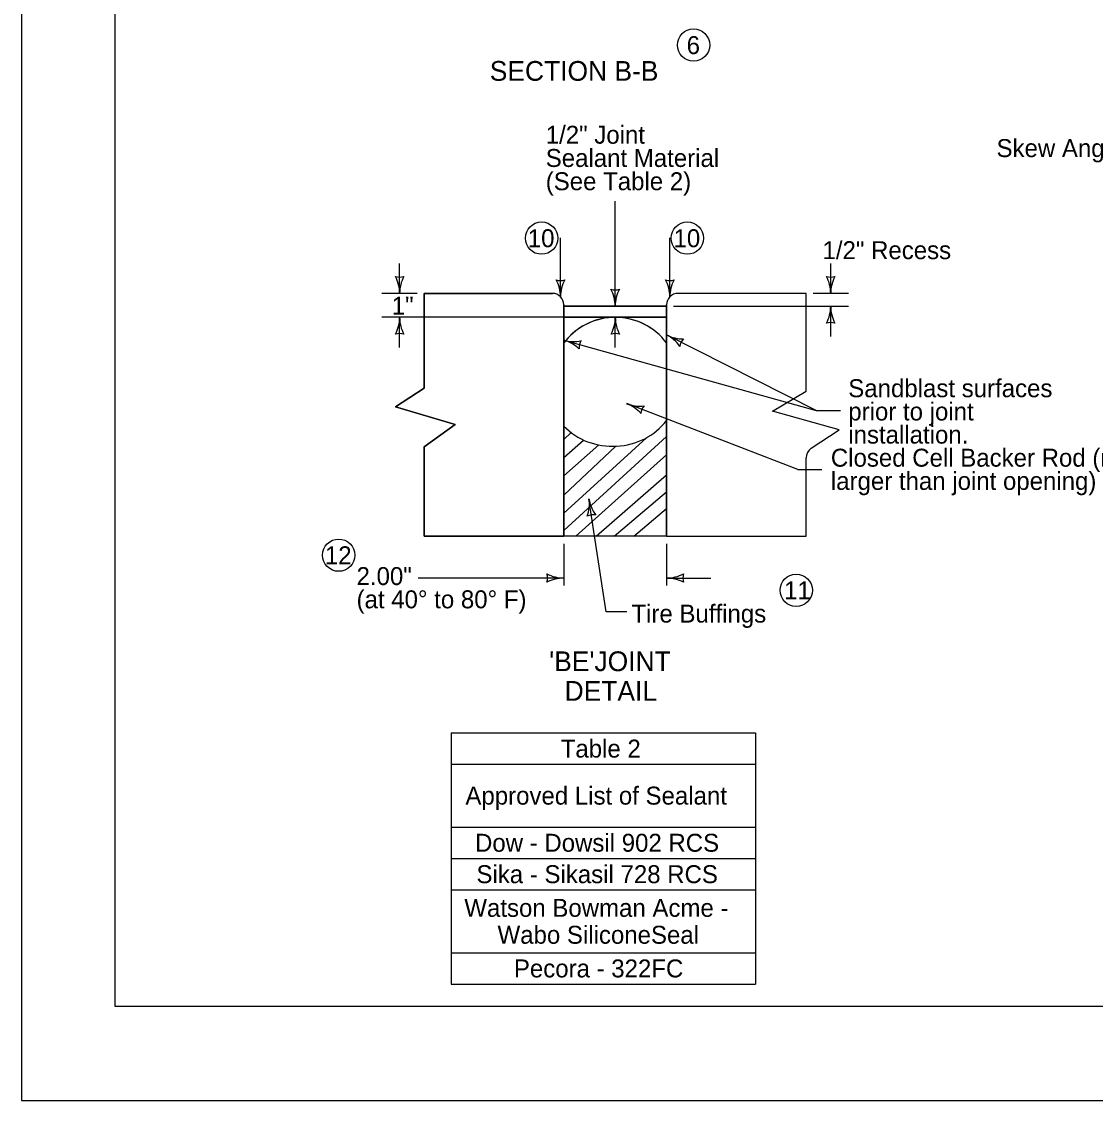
# Model space of a CAD drawing. Extents: x -2135039 to -2120895, y -2139150 to -2136566.
# Drawn here: x -2124239 to -2123042, y -2139150 to -2137949 of the extents above; entities that cross this region are included whole.
import ezdxf

# ---------------------------------------------------------------- set-up
doc = ezdxf.new("R2010")
doc.units = 0
for name, color, linetype in [('Default', 7, 'Continuous'), ('dsnDOTLogo', 7, 'Continuous'), ('Level 1', 7, 'Continuous'), ('Level 2', 7, 'Continuous'), ('Level 3', 7, 'Continuous')]:
    doc.layers.add(name, color=color, linetype=linetype)

msp = doc.modelspace()

# ---------------------------------------------------------------- linework, layer by layer
at = {"layer": 'Default'}
for p, q in [((-2123790.4, -2138357), (-2123790.4, -2138251.4)), ((-2123790.4, -2138251.4), (-2123647.5, -2138251.4)), ((-2123634.8, -2138264.2), (-2123634.8, -2138265.6)), ((-2123634.8, -2138294.2), (-2123634.8, -2138265.6)), ((-2123634.8, -2138265.6), (-2123634.8, -2138521.9)), ((-2123634.8, -2138265.6), (-2123520.3, -2138265.6)), ((-2123520.3, -2138521.9), (-2123520.3, -2138264.2)), ((-2123520.3, -2138265.6), (-2123520.3, -2138300.4)), ((-2123520.3, -2138265.6), (-2123520.3, -2138278)), ((-2123520.3, -2138278), (-2123634.8, -2138278)), ((-2123634.8, -2138278), (-2123634.8, -2138306.6)), ((-2123634.8, -2138306.6), (-2123634.8, -2138278)), ((-2123577.9, -2138278), (-2123577.2, -2138278)), ((-2123520.3, -2138306.5), (-2123520.3, -2138278)), ((-2123520.3, -2138278), (-2123520.3, -2138306.6)), ((-2123822.2, -2138377.8), (-2123790.4, -2138357)), ((-2123755.7, -2138397.6), (-2123822.2, -2138377.8)), ((-2123790.4, -2138422.2), (-2123755.7, -2138397.6)), ((-2123634.9, -2138414.2), (-2123626.7, -2138406.2)), ((-2123634.9, -2138496.1), (-2123542.7, -2138412.2)), ((-2123634.9, -2138434.3), (-2123612.7, -2138414.7)), ((-2123634.7, -2138515.6), (-2123520.5, -2138410.9)), ((-2123790.4, -2138521.9), (-2123790.4, -2138422.2)), ((-2123634.9, -2138476.1), (-2123576.9, -2138421.6)), ((-2123634.8, -2138454.7), (-2123595.6, -2138419.9)), ((-2123621.4, -2138521.9), (-2123520.1, -2138431)), ((-2123364.7, -2138521.9), (-2123364.7, -2138434.6)), ((-2123598.8, -2138522), (-2123520.3, -2138453.4)), ((-2123578.5, -2138522), (-2123520.3, -2138472.6)), ((-2123556.7, -2138521.9), (-2123520.2, -2138491.1)), ((-2123520.3, -2138521.9), (-2123790.4, -2138521.9)), ((-2123520.3, -2138521.9), (-2123364.7, -2138521.9))]:
    msp.add_line(p, q, dxfattribs=at)
for points in [[(-2123359, -2138423.9), (-2123328, -2138403.3), (-2123402.3, -2138382.4), (-2123364.8, -2138360.4), (-2123364.7, -2138251.4), (-2123507.5, -2138251.4)], [(-2123520.3, -2138297.6), (-2123520.3, -2138289.4), (-2123520.3, -2138289.3), (-2123520.3, -2138289.2), (-2123520.3, -2138278), (-2123520.3, -2138265.6), (-2123634.8, -2138265.6), (-2123634.8, -2138306.6)], [(-2123520.3, -2138264.2), (-2123520.3, -2138265.6), (-2123520.3, -2138300.4), (-2123520.3, -2138521.9), (-2123529.6, -2138521.9)], [(-2123634.8, -2138306.6), (-2123634.8, -2138278), (-2123577.7, -2138278)], [(-2123634.8, -2138306.6), (-2123634.8, -2138278), (-2123577.7, -2138278)], [(-2123634.8, -2138306.6), (-2123634.8, -2138278), (-2123577.7, -2138278)], [(-2123634.8, -2138306.6), (-2123634.8, -2138278), (-2123577.7, -2138278)], [(-2123634.8, -2138306.6), (-2123634.8, -2138278), (-2123577.7, -2138278)], [(-2123577.4, -2138278), (-2123520.3, -2138278), (-2123520.3, -2138306.6)], [(-2123577.4, -2138278), (-2123520.3, -2138278), (-2123520.3, -2138289.2), (-2123520.3, -2138289.3), (-2123520.3, -2138289.4), (-2123520.3, -2138306.6)], [(-2123520.3, -2138306.6), (-2123520.3, -2138306.5), (-2123520.3, -2138306.5), (-2123520.3, -2138297.7)]]:
    msp.add_lwpolyline(points, dxfattribs=at)
for centre, radius, start, end in [((-2123647.5, -2138264.2), 12.8, 0, 90), ((-2123507.5, -2138264.2), 12.8, 90, 180), ((-2123577.5, -2138349.5), 71.5, 36.8603, 143.1397), ((-2123577.5, -2138349.5), 71.5, 90.1278, 143.139), ((-2123577.5, -2138349.5), 71.5, 90.1278, 143.139), ((-2123577.5, -2138349.5), 71.5, 90.1278, 143.1385), ((-2123577.5, -2138349.5), 71.5, 90.1278, 143.1385), ((-2123577.5, -2138349.5), 71.5, 98.1344, 143.1385), ((-2123577.5, -2138349.5), 71.5, 90.3158, 140.4626), ((-2123577.5, -2138349.5), 71.5, 90.1278, 98.1344), ((-2123577.5, -2138349.5), 71.5, 36.8603, 89.8704), ((-2123577.5, -2138349.5), 71.5, 36.8603, 89.8704), ((-2123577.5, -2138349.5), 71.5, 36.8603, 89.6842), ((-2123577.5, -2138349.5), 71.5, 140.4626, 143.1385), ((-2123538.8, -2138333.3), 40.2, 62.5774, 63.2482), ((-2123502.7, -2138261.6), 40.2, 243.2482, 243.9147), ((-2123351.9, -2138434.6), 12.8, 123.5371, 180), ((-2123351.9, -2138434.6), 12.8, 123.5371, 180)]:
    msp.add_arc(centre, radius, start, end, dxfattribs=at)
for centre, start_param, end_param in [((-2123580.2, -2138344.6), 0.606648, 0.606655), ((-2123580.2, -2138355), 3.864857, 5.676062)]:
    msp.add_ellipse(centre, major_axis=(72.8, 0), ratio=0.91682, start_param=start_param, end_param=end_param, dxfattribs=at)
at = {"layer": 'dsnDOTLogo'}
msp.add_lwpolyline([(-2124239, -2139150.4), (-2120895, -2139150.4), (-2120895, -2136566.4), (-2124239, -2136566.4)], close=True, dxfattribs=at)
at = {"layer": 'Level 1'}
msp.add_lwpolyline([(-2124134.5, -2137035.9), (-2120999.5, -2137035.9), (-2120999.5, -2139045.9), (-2124134.5, -2139045.9)], close=True, dxfattribs=at)
at = {"layer": 'Level 2'}
for p, q in [((-2123760.3, -2138741), (-2123421, -2138741)), ((-2123760.3, -2138741), (-2123760.3, -2139020.9)), ((-2123421, -2138741), (-2123421, -2139020.9)), ((-2123760.3, -2138775.9), (-2123421, -2138775.9)), ((-2123760.3, -2138845.9), (-2123421, -2138845.9)), ((-2123760.3, -2138880.9), (-2123421, -2138880.9)), ((-2123760.3, -2138915.9), (-2123421, -2138915.9)), ((-2123760.3, -2138985.9), (-2123421, -2138985.9)), ((-2123760.3, -2139020.9), (-2123421, -2139020.9))]:
    msp.add_line(p, q, dxfattribs=at)
for points in [[(-2123647.5, -2138251.4), (-2123790.4, -2138251.4), (-2123790.4, -2138357), (-2123822.2, -2138377.8), (-2123755.7, -2138397.6), (-2123790.4, -2138422.2), (-2123790.4, -2138521.9), (-2123634.8, -2138521.9), (-2123634.8, -2138306.6)], [(-2123359, -2138423.9), (-2123328, -2138403.3), (-2123402.3, -2138382.4), (-2123364.8, -2138360.4), (-2123364.7, -2138251.4), (-2123507.5, -2138251.4)], [(-2123634.8, -2138306.6), (-2123634.8, -2138303.5), (-2123634.8, -2138278), (-2123634.8, -2138265.6), (-2123634.8, -2138264.2)], [(-2123520.3, -2138264.2), (-2123520.3, -2138265.6), (-2123520.3, -2138265.6), (-2123520.3, -2138271.9), (-2123520.3, -2138297.7), (-2123520.3, -2138300.4), (-2123520.3, -2138521.9), (-2123364.7, -2138521.9), (-2123364.7, -2138434.6)]]:
    msp.add_lwpolyline(points, dxfattribs=at)
for centre in [(-2123490.2, -2137974.7), (-2123659.5, -2138189.8), (-2123497.1, -2138189.8), (-2123885.6, -2138543), (-2123375.8, -2138582.1)]:
    msp.add_circle(centre, 18, dxfattribs=at)
for centre, radius, start, end in [((-2123817.7, -2138217.7), 15.5, 252.2666, 287.7333), ((-2123857.9, -2138251.4), 40.2, 360, 28.0725), ((-2123777.5, -2138251.4), 40.2, 151.9275, 180), ((-2123638.5, -2138221.5), 15.5, 252.2666, 287.7333), ((-2123678.7, -2138255.2), 40.2, 360, 28.0725), ((-2123598.3, -2138255.2), 40.2, 151.9275, 180), ((-2123516.6, -2138221.5), 15.5, 252.2666, 287.7333), ((-2123556.8, -2138255.2), 40.2, 360, 28.0725), ((-2123476.4, -2138255.2), 40.2, 151.9275, 180), ((-2123337.4, -2138217.7), 15.5, 252.2666, 287.7333), ((-2123377.6, -2138251.4), 40.2, 360, 28.0725), ((-2123297.2, -2138251.4), 40.2, 151.9275, 180), ((-2123577.5, -2138232), 15.5, 252.2666, 287.7333), ((-2123617.7, -2138265.6), 40.2, 360, 28.0725), ((-2123537.4, -2138265.6), 40.2, 151.9275, 180), ((-2123647.5, -2138264.2), 12.8, 0, 90), ((-2123507.5, -2138264.2), 12.8, 90, 180), ((-2123377.6, -2138265.6), 40.2, 331.9275, 0), ((-2123297.2, -2138265.6), 40.2, 180, 208.0725), ((-2123857.9, -2138278), 40.2, 331.9275, 0), ((-2123777.5, -2138278), 40.2, 180, 208.0725), ((-2123617.6, -2138278), 40.2, 331.9275, 0), ((-2123537.2, -2138278), 40.2, 180, 208.0725), ((-2123337.4, -2138299.3), 15.5, 72.2667, 107.7334), ((-2123817.7, -2138311.6), 15.5, 72.2667, 107.7334), ((-2123577.4, -2138311.6), 15.5, 72.2667, 107.7334), ((-2123645.6, -2138342.2), 40.2, 46.3768, 74.4493), ((-2123624, -2138264.8), 40.2, 254.4493, 282.5218), ((-2123577.5, -2138349.5), 71.5, 143.1385, 143.139), ((-2123602.3, -2138312.5), 15.5, 146.716, 182.1827), ((-2123538.4, -2138333.5), 40.2, 35.1757, 63.2482), ((-2123502.2, -2138261.8), 40.2, 243.2482, 271.3206), ((-2123490.2, -2138312.8), 15.5, 135.5148, 170.9815), ((-2123579.1, -2138411.6), 40.2, 40.8833, 68.9558), ((-2123550.3, -2138336.7), 40.2, 248.9558, 277.0283), ((-2123533.3, -2138386.2), 15.5, 141.2225, 176.6892), ((-2123351.9, -2138434.6), 12.8, 123.5371, 179.992), ((-2123351.9, -2138434.6), 12.8, 179.992, 180), ((-2123646.5, -2138486.2), 40.2, 340.591, 8.6635), ((-2123567, -2138474.1), 40.2, 188.6635, 216.7359), ((-2123601.7, -2138513.4), 15.5, 80.9301, 116.3968), ((-2123668.4, -2138568.5), 15.5, 342.2666, 17.7333), ((-2123634.8, -2138528.3), 40.2, 241.9275, 270), ((-2123634.8, -2138608.7), 40.2, 90, 118.0725), ((-2123520.3, -2138528.3), 40.2, 270, 298.0725), ((-2123520.3, -2138608.7), 40.2, 61.9275, 90), ((-2123486.6, -2138568.5), 15.5, 162.2666, 197.7333)]:
    msp.add_arc(centre, radius, start, end, dxfattribs=at)
at = {"layer": 'Level 3'}
for p, q in [((-2123577.5, -2138265.6), (-2123577.5, -2138148.7)), ((-2123638.5, -2138255.2), (-2123638.5, -2138189.6)), ((-2123516.6, -2138255.2), (-2123516.6, -2138189.6)), ((-2123817.7, -2138251.4), (-2123817.7, -2138217.9)), ((-2123337.4, -2138251.4), (-2123337.4, -2138217.9)), ((-2123798, -2138251.4), (-2123837.4, -2138251.4)), ((-2123317.7, -2138251.4), (-2123357.1, -2138251.4)), ((-2123512.7, -2138265.6), (-2123317.7, -2138265.6)), ((-2123337.4, -2138299.2), (-2123337.4, -2138265.6)), ((-2123602.3, -2138278), (-2123837.4, -2138278)), ((-2123817.7, -2138311.5), (-2123817.7, -2138278)), ((-2123577.4, -2138311.5), (-2123577.4, -2138278)), ((-2123634.8, -2138303.5), (-2123353.4, -2138381.8)), ((-2123353.4, -2138381.8), (-2123520.3, -2138297.7)), ((-2123374.1, -2138447.5), (-2123564.7, -2138374.1)), ((-2123353.4, -2138381.8), (-2123326.4, -2138382)), ((-2123374.1, -2138447.5), (-2123347.1, -2138447.7)), ((-2123587.6, -2138606.1), (-2123606.8, -2138480.1)), ((-2123634.8, -2138530.4), (-2123634.8, -2138576.8)), ((-2123520.3, -2138530.2), (-2123520.3, -2138576.8)), ((-2123634.8, -2138568.5), (-2123797, -2138568.5)), ((-2123520.3, -2138568.5), (-2123470.8, -2138568.5)), ((-2123564.6, -2138606.1), (-2123587.6, -2138606.1))]:
    msp.add_line(p, q, dxfattribs=at)

# ---------------------------------------------------------------- texts
at = {"layer": 'Level 2'}
for s, p in [("   'BE'JOINT ", (-2123675.6, -2138672.2)), ('   DETAIL', (-2123658.4, -2138705.2))]:
    msp.add_text(s, height=22, dxfattribs=at).set_placement(p)
at = {"layer": 'Level 3'}
for s, height, p in [('6', 20, (-2123497.9, -2137984.8)), ('SECTION B-B', 22, (-2123717.3, -2138014.5)), ('1/2" Joint', 20, (-2123654.9, -2138084.6)), ('Skew Angle', 20, (-2123152.6, -2138099.5)), ('Sealant Material', 20, (-2123654.9, -2138110.5)), ('(See Table 2)', 20, (-2123654.9, -2138136.4)), ('10', 20, (-2123674.9, -2138199.9)), ('10', 20, (-2123512.5, -2138199.9)), ('1/2" Recess', 20, (-2123346.5, -2138213.2)), ('1"', 20, (-2123826.5, -2138275.1)), ('Sandblast surfaces ', 20, (-2123317.8, -2138367)), ('prior to joint ', 20, (-2123317.8, -2138392.9)), ('installation.', 20, (-2123317.8, -2138418.7)), ('Closed Cell Backer Rod (minimum 25%', 20, (-2123337.2, -2138444.4)), ('larger than joint opening)', 20, (-2123337.2, -2138470.3)), ('12', 20, (-2123901, -2138553.1)), ('2.00"', 20, (-2123865.7, -2138576.3)), ('11', 20, (-2123389.4, -2138592.2)), ('(at 40° to 80° F)', 20, (-2123865.7, -2138602.2)), ('Tire Buffings', 20, (-2123559.4, -2138618.1)), ('Table 2', 20, (-2123638.2, -2138768.5)), ('Approved List of Sealant', 20, (-2123744.4, -2138820.9)), ('Dow - Dowsil 902 RCS', 20, (-2123733.7, -2138873.4)), ('Sika - Sikasil 728 RCS', 20, (-2123732.1, -2138908.4)), ('Watson Bowman Acme - ', 20, (-2123745.6, -2138945.9)), ('Wabo SiliconeSeal', 20, (-2123708.6, -2138975.9)), ('Pecora - 322FC', 20, (-2123690.4, -2139013.4))]:
    msp.add_text(s, height=height, dxfattribs=at).set_placement(p)

doc.saveas('drawing.dxf')
